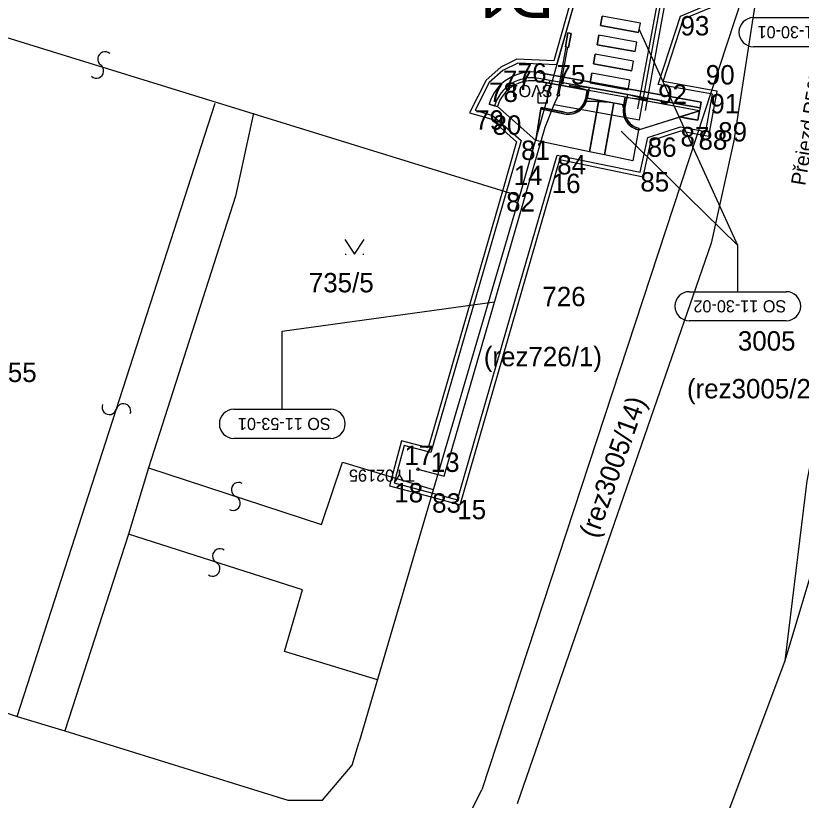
# Model space of a CAD drawing. Extents: x -728800 to -728100, y -1073200 to -1072700.
# Drawn here: x -728549.49 to -728508.97, y -1073097.26 to -1073056.8 of the extents above; entities that cross this region are included whole.
import ezdxf

# ---------------------------------------------------------------- set-up
doc = ezdxf.new("R2010")
doc.units = 0
for name, color, linetype in [('_NOR-návrh tenká obec', 7, 'Continuous'), ('_NOR-VDZ', 7, 'Continuous'), ('_NOR-šraf_+-0', 7, 'Continuous'), ('_NOR-šraf_+12', 7, 'Continuous'), ('_NOR-šraf_+6', 7, 'Continuous'), ('_NOR-šraf_bezbariéra', 7, 'Continuous'), ('_NOR-šraf_chodník', 7, 'Continuous'), ('_NOR-šraf_signální pás', 7, 'Continuous'), ('_NOR-šraf_varovný pás', 7, 'Continuous'), ('_NOR-šraf_vozovka', 7, 'Continuous'), ('_NOR-šraf_zeleň', 7, 'Continuous'), ('A2_OBVOD STAVBY', 7, 'Continuous'), ('B1_body_poloha', 7, 'Continuous'), ('B2_body_číslo', 7, 'Continuous'), ('B6_JŽM', 7, 'Continuous'), ('Default', 7, 'Continuous'), ('K_01_Hranice parcel', 7, 'Continuous'), ('K_02_Parcelní čísla', 7, 'Continuous'), ('K_03_Značky druhu pozemku', 7, 'Continuous'), ('KOS_kabelová trasa VO', 7, 'Continuous'), ('KOS_nové prvky VO', 7, 'Continuous'), ('KTA_členění PS a SO', 7, 'Continuous'), ('ZA_02_Dočasný_do_1_roku', 7, 'Continuous')]:
    doc.layers.add(name, color=color, linetype=linetype)

msp = doc.modelspace()

# ---------------------------------------------------------------- linework, layer by layer
at = {"layer": '_NOR-návrh tenká obec'}
for p, q in [((-728519.325, -1073057.313), (-728519.235, -1073056.821)), ((-728517.267, -1073057.179), (-728519.235, -1073056.821)), ((-728517.357, -1073057.671), (-728519.325, -1073057.313)), ((-728517.357, -1073057.671), (-728517.267, -1073057.179)), ((-728519.504, -1073058.296), (-728519.414, -1073057.805)), ((-728517.447, -1073058.163), (-728519.414, -1073057.805)), ((-728517.536, -1073058.655), (-728519.504, -1073058.296)), ((-728517.536, -1073058.655), (-728517.447, -1073058.163)), ((-728519.683, -1073059.28), (-728519.593, -1073058.788)), ((-728517.626, -1073059.147), (-728519.593, -1073058.788)), ((-728517.716, -1073059.639), (-728519.683, -1073059.28)), ((-728517.716, -1073059.639), (-728517.626, -1073059.147)), ((-728519.862, -1073060.264), (-728519.773, -1073059.772)), ((-728517.805, -1073060.131), (-728519.773, -1073059.772)), ((-728517.895, -1073060.623), (-728519.862, -1073060.264)), ((-728517.895, -1073060.623), (-728517.805, -1073060.131)), ((-728520.013, -1073060.643), (-728520.904, -1073060.404)), ((-728520.904, -1073060.404), (-728519.907, -1073060.51)), ((-728518.045, -1073061.002), (-728518.124, -1073061.524)), ((-728517.967, -1073061.016), (-728518.077, -1073061.532)), ((-728517.967, -1073061.016), (-728516.969, -1073061.122)), ((-728516.969, -1073061.122), (-728517.94, -1073060.869)), ((-728522.668, -1073063.246), (-728524.642, -1073061.491)), ((-728520.176, -1073061.464), (-728520.242, -1073061.417)), ((-728519.416, -1073061.159), (-728519.9, -1073063.819)), ((-728518.629, -1073061.302), (-728519.117, -1073063.982)), ((-728514.211, -1073061.701), (-728514.301, -1073062.192)), ((-728518.116, -1073061.988), (-728518.039, -1073061.965)), ((-728517.366, -1073062.682), (-728515.241, -1073062.021)), ((-728517.366, -1073062.682), (-728517.657, -1073064.284)), ((-728517.29, -1073062.698), (-728517.29, -1073062.698))]:
    msp.add_line(p, q, dxfattribs=at)
for points in [[(-728514.184, -1073061.553), (-728514.13, -1073061.258), (-728522.452, -1073059.741)], [(-728514.184, -1073061.553), (-728514.211, -1073061.701), (-728522.533, -1073060.184)], [(-728514.184, -1073061.553), (-728522.506, -1073060.036)], [(-728520.918, -1073060.478), (-728520.891, -1073060.331)], [(-728520.087, -1073061.05), (-728520.013, -1073060.643)], [(-728519.907, -1073060.51), (-728520.008, -1073061.064)], [(-728518.117, -1073061.395), (-728520.006, -1073061.051)], [(-728518.045, -1073061.002), (-728518.141, -1073061.525)], [(-728517.94, -1073060.869), (-728518.062, -1073061.539)], [(-728516.956, -1073061.048), (-728516.983, -1073061.195)], [(-728525.075, -1073061.366), (-728524.786, -1073061.45)], [(-728524.642, -1073061.491), (-728524.786, -1073061.45)], [(-728521.201, -1073061.863), (-728522.401, -1073061.607), (-728522.388, -1073061.528), (-728521.184, -1073061.785)], [(-728514.301, -1073062.192), (-728515.241, -1073062.021)], [(-728517.349, -1073062.604), (-728517.366, -1073062.682)]]:
    msp.add_lwpolyline(points, dxfattribs=at)
for centre, radius, start, end in [((-728522.865, -1073062.004), 2.3, 79.6716, 163.9062), ((-728522.865, -1073062.004), 2, 79.6716, 163.9062), ((-728522.865, -1073062.004), 1.85, 79.6716, 163.9062), ((-728521.651, -1073060.659), 1.639, 331.5487, 0.5464), ((-728522.656, -1073060.141), 2.771, 332.0344, 349.2616), ((-728520.992, -1073060.885), 1, 257.9461, 349.6716), ((-728520.992, -1073060.885), 0.92, 257.9461, 349.6716), ((-728517.157, -1073061.704), 1, 169.6716, 257.9461), ((-728517.115, -1073061.648), 1.016, 172.9753, 198.8554), ((-728517.182, -1073061.755), 0.922, 166.0226, 193.9069), ((-728517.157, -1073061.704), 0.92, 169.6716, 257.9461)]:
    msp.add_arc(centre, radius, start, end, dxfattribs=at)
at = {"layer": '_NOR-VDZ'}
for p, q in [((-728519.325, -1073057.313), (-728519.235, -1073056.821)), ((-728517.267, -1073057.179), (-728519.235, -1073056.821)), ((-728517.357, -1073057.671), (-728519.325, -1073057.313)), ((-728517.357, -1073057.671), (-728517.267, -1073057.179)), ((-728519.504, -1073058.296), (-728519.414, -1073057.805)), ((-728517.447, -1073058.163), (-728519.414, -1073057.805)), ((-728517.536, -1073058.655), (-728519.504, -1073058.296)), ((-728517.536, -1073058.655), (-728517.447, -1073058.163)), ((-728519.683, -1073059.28), (-728519.593, -1073058.788)), ((-728517.626, -1073059.147), (-728519.593, -1073058.788)), ((-728517.716, -1073059.639), (-728519.683, -1073059.28)), ((-728517.716, -1073059.639), (-728517.626, -1073059.147)), ((-728519.862, -1073060.264), (-728519.773, -1073059.772)), ((-728517.805, -1073060.131), (-728519.773, -1073059.772)), ((-728517.895, -1073060.623), (-728519.862, -1073060.264)), ((-728517.895, -1073060.623), (-728517.805, -1073060.131))]:
    msp.add_line(p, q, dxfattribs=at)
for points in [[(-728517.357, -1073057.671), (-728517.267, -1073057.179), (-728519.235, -1073056.821), (-728519.325, -1073057.313), (-728517.357, -1073057.671)], [(-728517.536, -1073058.655), (-728517.447, -1073058.163), (-728519.414, -1073057.805), (-728519.504, -1073058.296), (-728517.536, -1073058.655)], [(-728517.716, -1073059.639), (-728517.626, -1073059.147), (-728519.593, -1073058.788), (-728519.683, -1073059.28), (-728517.716, -1073059.639)], [(-728517.895, -1073060.623), (-728517.805, -1073060.131), (-728519.773, -1073059.772), (-728519.862, -1073060.264), (-728517.895, -1073060.623)]]:
    msp.add_lwpolyline(points, dxfattribs=at)
at = {"layer": '_NOR-šraf_+-0'}
for points in [[(-728518.039, -1073061.965), (-728518.077, -1073061.977), (-728518.116, -1073061.988)], [(-728517.366, -1073062.682), (-728517.349, -1073062.604)]]:
    msp.add_lwpolyline(points, dxfattribs=at)
for radius in [1, 0.92]:
    msp.add_arc((-728517.157, -1073061.704), radius, 196.5034, 257.9461, dxfattribs=at)
at = {"layer": '_NOR-šraf_+12'}
msp.add_line((-728524.786, -1073061.45), (-728524.642, -1073061.491), dxfattribs=at)
for points in [[(-728522.533, -1073060.184), (-728521.989, -1073060.283), (-728521.929, -1073060.141), (-728522.506, -1073060.036)], [(-728520.918, -1073060.478), (-728520.904, -1073060.404), (-728520.891, -1073060.331), (-728521.929, -1073060.141), (-728521.989, -1073060.283), (-728520.918, -1073060.478)], [(-728516.983, -1073061.195), (-728516.969, -1073061.122), (-728516.956, -1073061.048), (-728514.184, -1073061.553), (-728514.211, -1073061.701), (-728516.983, -1073061.195)]]:
    msp.add_lwpolyline(points, dxfattribs=at)
for radius in [2, 1.85]:
    msp.add_arc((-728522.865, -1073062.004), radius, 79.6716, 163.9062, dxfattribs=at)
at = {"layer": '_NOR-šraf_+6'}
for points in [[(-728521.184, -1073061.785), (-728522.388, -1073061.528), (-728522.401, -1073061.607)], [(-728520.176, -1073061.464), (-728520.209, -1073061.441), (-728520.211, -1073061.439), (-728520.242, -1073061.417)], [(-728522.401, -1073061.607), (-728521.201, -1073061.863)]]:
    msp.add_lwpolyline(points, dxfattribs=at)
for radius in [1, 0.92]:
    msp.add_arc((-728520.992, -1073060.885), radius, 257.9461, 324.641, dxfattribs=at)
at = {"layer": '_NOR-šraf_bezbariéra'}
msp.add_lwpolyline([(-728519.934, -1073060.658), (-728519.907, -1073060.51), (-728517.94, -1073060.869), (-728517.967, -1073061.016), (-728519.934, -1073060.658)], dxfattribs=at)
at = {"layer": '_NOR-šraf_chodník'}
for p, q in [((-728518.145, -1073061.548), (-728518.197, -1073061.381)), ((-728518.197, -1073061.381), (-728518.145, -1073061.548))]:
    msp.add_line(p, q, dxfattribs=at)
for points in [[(-728520.008, -1073061.064), (-728520.006, -1073061.051), (-728519.416, -1073061.159), (-728519.429, -1073061.233), (-728520.045, -1073061.206)], [(-728520.045, -1073061.206), (-728519.429, -1073061.233), (-728519.9, -1073063.819), (-728522.668, -1073063.246)], [(-728519.117, -1073063.982), (-728518.629, -1073061.302), (-728518.197, -1073061.381)], [(-728518.197, -1073061.381), (-728518.117, -1073061.395), (-728518.141, -1073061.525)], [(-728522.668, -1073063.246), (-728522.401, -1073061.607), (-728521.201, -1073061.863)], [(-728517.37, -1073062.681), (-728517.366, -1073062.682), (-728517.657, -1073064.284), (-728519.117, -1073063.982)]]:
    msp.add_lwpolyline(points, dxfattribs=at)
for centre, start, end in [((-728520.992, -1073060.885), 341.2678, 349.6716), ((-728520.992, -1073060.885), 257.9461, 324.641), ((-728520.992, -1073060.885), 324.641, 341.2678), ((-728517.157, -1073061.704), 169.6716, 171.0403), ((-728517.157, -1073061.704), 171.0403, 196.5034), ((-728517.157, -1073061.704), 196.5034, 257.6848)]:
    msp.add_arc(centre, 1, start, end, dxfattribs=at)
at = {"layer": '_NOR-šraf_signální pás'}
for points in [[(-728519.429, -1073061.233), (-728518.877, -1073061.257), (-728518.629, -1073061.302), (-728519.117, -1073063.982), (-728519.9, -1073063.819), (-728519.429, -1073061.233)], [(-728519.416, -1073061.159), (-728518.877, -1073061.257), (-728519.429, -1073061.233), (-728519.416, -1073061.159)]]:
    msp.add_lwpolyline(points, dxfattribs=at)
at = {"layer": '_NOR-šraf_varovný pás'}
msp.add_lwpolyline([(-728520.006, -1073061.051), (-728519.416, -1073061.159), (-728518.629, -1073061.302), (-728518.117, -1073061.395), (-728518.045, -1073061.002), (-728519.934, -1073060.658), (-728520.006, -1073061.051), (-728520.006, -1073061.051)], dxfattribs=at)
at = {"layer": '_NOR-šraf_vozovka'}
for points in [[(-728522.452, -1073059.741), (-728514.13, -1073061.258), (-728514.184, -1073061.553), (-728516.956, -1073061.048), (-728517.94, -1073060.869), (-728519.907, -1073060.51), (-728522.506, -1073060.036)], [(-728524.786, -1073061.45), (-728525.075, -1073061.366), (-728525.075, -1073061.366)]]:
    msp.add_lwpolyline(points, dxfattribs=at)
for radius in [2.3, 2]:
    msp.add_arc((-728522.865, -1073062.004), radius, 79.6716, 163.9062, dxfattribs=at)
at = {"layer": '_NOR-šraf_zeleň'}
for points in [[(-728522.533, -1073060.184), (-728522.115, -1073060.26), (-728522.341, -1073060.799), (-728522.56, -1073060.799), (-728522.56, -1073061.299), (-728522.31, -1073061.299), (-728522.06, -1073061.299), (-728522.06, -1073060.799), (-728522.07, -1073060.799), (-728521.863, -1073060.306), (-728520.013, -1073060.643), (-728520.087, -1073061.05)], [(-728517.349, -1073062.604), (-728517.366, -1073062.682), (-728514.211, -1073061.701), (-728517.967, -1073061.016), (-728518.062, -1073061.539)], [(-728521.184, -1073061.785), (-728522.388, -1073061.528), (-728522.401, -1073061.607), (-728522.668, -1073063.246), (-728524.642, -1073061.491)], [(-728514.832, -1073062.096), (-728514.301, -1073062.192), (-728514.211, -1073061.701), (-728515.241, -1073062.021), (-728514.832, -1073062.096), (-728514.832, -1073062.096)]]:
    msp.add_lwpolyline(points, dxfattribs=at)
for centre, radius, start, end in [((-728522.865, -1073062.004), 1.85, 79.6716, 163.9062), ((-728520.992, -1073060.885), 0.92, 324.641, 349.6716), ((-728520.992, -1073060.885), 0.92, 257.9461, 324.641), ((-728517.157, -1073061.704), 0.92, 169.6716, 196.5034), ((-728517.157, -1073061.704), 0.92, 196.5034, 257.9461)]:
    msp.add_arc(centre, radius, start, end, dxfattribs=at)
at = {"layer": 'A2_OBVOD STAVBY'}
msp.add_lwpolyline([(-728520.331, -1073054.186), (-728521.735, -1073059.131), (-728523.635, -1073059.049), (-728524.468, -1073059.462), (-728525.229, -1073060.125), (-728526.082, -1073061.804), (-728524.989, -1073062.12), (-728523.652, -1073063.308), (-728524.386, -1073065.843), (-728528.221, -1073079.089), (-728529.585, -1073078.721), (-728530.21, -1073081.039), (-728528.058, -1073081.619), (-728526.571, -1073082.019), (-728521.417, -1073064.22), (-728517.12, -1073065.11), (-728516.715, -1073063.238), (-728515.187, -1073062.742), (-728514.306, -1073062.903), (-728513.737, -1073063.007), (-728513.316, -1073060.695), (-728513.62, -1073060.639), (-728516.085, -1073060.19), (-728515.041, -1073056.967), (-728511.798, -1073055.597)], dxfattribs=at)
at = {"layer": 'B1_body_poloha'}
for p, q in [((-728515.2, -1073056.82), (-728515.2, -1073056.82)), ((-728523.59, -1073059.25), (-728523.59, -1073059.25)), ((-728521.59, -1073059.34), (-728521.59, -1073059.34)), ((-728524.36, -1073059.63), (-728524.36, -1073059.63)), ((-728525.07, -1073060.25), (-728525.07, -1073060.25)), ((-728516.35, -1073060.35), (-728516.35, -1073060.35)), ((-728513.66, -1073060.84), (-728513.66, -1073060.84)), ((-728513.55, -1073060.86), (-728513.55, -1073060.86)), ((-728525.79, -1073061.68), (-728525.79, -1073061.68)), ((-728524.89, -1073061.94), (-728524.89, -1073061.94)), ((-728515.2, -1073062.54), (-728515.2, -1073062.54)), ((-728514.27, -1073062.71), (-728514.27, -1073062.71)), ((-728516.89, -1073063.08), (-728516.89, -1073063.08)), ((-728513.9, -1073062.77), (-728513.9, -1073062.77)), ((-728523.42, -1073063.24), (-728523.42, -1073063.24)), ((-728521.56, -1073063.99), (-728521.56, -1073063.99)), ((-728523.8, -1073064.54), (-728523.8, -1073064.54)), ((-728521.84, -1073064.95), (-728521.84, -1073064.95)), ((-728517.27, -1073064.87), (-728517.27, -1073064.87)), ((-728524.19, -1073065.9), (-728524.19, -1073065.9)), ((-728529.44, -1073078.97), (-728529.44, -1073078.97)), ((-728528.08, -1073079.33), (-728528.08, -1073079.33)), ((-728529.96, -1073080.9), (-728529.96, -1073080.9)), ((-728528.01, -1073081.43), (-728528.01, -1073081.43)), ((-728526.71, -1073081.77), (-728526.71, -1073081.77))]:
    msp.add_line(p, q, dxfattribs=at)
at = {"layer": 'K_01_Hranice parcel'}
for p, q in [((-728510.66, -1073051.71), (-728525.44, -1073096.73)), ((-728519.8, -1073053.05), (-728523.51, -1073066.11)), ((-728523.51, -1073066.11), (-728551.004, -1073057.612)), ((-728549.411, -1073092.938), (-728539.196, -1073061.32)), ((-728523.51, -1073066.11), (-728531.77, -1073094.25)), ((-728513.61, -1073068.54), (-728523.622, -1073097.442))]:
    msp.add_line(p, q, dxfattribs=at)
for points in [[(-728510.66, -1073051.71), (-728512.45, -1073063.25), (-728513.61, -1073068.54)], [(-728503.24, -1073052.34), (-728506.32, -1073069.08), (-728508.676, -1073080.788), (-728509.816, -1073090.065)], [(-728537.214, -1073061.821), (-728538.146, -1073066.111), (-728542.63, -1073080.116), (-728543.663, -1073083.544), (-728546.946, -1073093.688)], [(-728504.87, -1073073.55), (-728509.816, -1073090.065), (-728516.822, -1073108.739), (-728518.032, -1073119.517), (-728508.074, -1073118.154), (-728495.997, -1073074.887)], [(-728579.353, -1073076.384), (-728583.789, -1073102.649), (-728543.041, -1073118.426), (-728537.574, -1073120.982), (-728525.44, -1073096.73)], [(-728542.63, -1073080.116), (-728533.711, -1073083.038), (-728532.624, -1073079.827), (-728527.948, -1073081.228)], [(-728569.191, -1073080.263), (-728570.895, -1073085.354), (-728570.206, -1073086.158), (-728561.23, -1073088.922), (-728549.411, -1073092.938), (-728546.946, -1073093.688), (-728535.442, -1073097.263), (-728533.661, -1073097.263), (-728532.131, -1073095.453), (-728531.77, -1073094.25)], [(-728530.83, -1073091.046), (-728535.614, -1073089.594), (-728534.69, -1073086.411), (-728543.663, -1073083.544)]]:
    msp.add_lwpolyline(points, dxfattribs=at)
at = {"layer": 'K_03_Značky druhu pozemku'}
for p, q in [((-728532.489, -1073069.096), (-728532.439, -1073069.096)), ((-728531.589, -1073069.096), (-728531.539, -1073069.096))]:
    msp.add_line(p, q, dxfattribs=at)
msp.add_lwpolyline([(-728532.514, -1073068.346), (-728532.014, -1073069.096), (-728531.514, -1073068.346)], dxfattribs=at)
for centre, start, end in [((-728544.88, -1073059.037), 47.7437, 234.0408), ((-728545.322, -1073059.646), 227.7437, 54.0408), ((-728544.654, -1073076.994), 158.8659, 345.163), ((-728543.927, -1073077.187), 338.8659, 165.163), ((-728537.988, -1073081.248), 60.9548, 247.2518), ((-728538.279, -1073081.942), 240.9548, 67.2518), ((-728538.956, -1073084.672), 54.1364, 240.4334), ((-728539.328, -1073085.327), 234.1364, 60.4334)]:
    msp.add_arc(centre, 0.376, start, end, dxfattribs=at)
at = {"layer": 'KOS_kabelová trasa VO'}
for p, q in [((-728515.932, -1073053.526), (-728517.409, -1073061.613)), ((-728515.538, -1073053.598), (-728517.015, -1073061.684))]:
    msp.add_line(p, q, dxfattribs=at)
for points in [[(-728528.739, -1073080.192), (-728527.396, -1073080.554), (-728522.184, -1073062.556), (-728521.71, -1073061.375), (-728517.306, -1073062.171), (-728515.639, -1073053.015), (-728515.016, -1073053.113), (-728515.09, -1073053.601)], [(-728521.71, -1073061.375), (-728521.499, -1073060.881)]]:
    msp.add_lwpolyline(points, dxfattribs=at)
at = {"layer": 'KOS_nové prvky VO'}
for p, q in [((-728521.527, -1073060.82), (-728521.089, -1073058.414)), ((-728521.452, -1073060.834), (-728521.014, -1073058.428))]:
    msp.add_line(p, q, dxfattribs=at)
msp.add_lwpolyline([(-728521.135, -1073058.406), (-728521.003, -1073057.682), (-728520.836, -1073057.712), (-728520.968, -1073058.436)], close=True, dxfattribs=at)
msp.add_lwpolyline([(-728520.968, -1073058.436), (-728520.836, -1073057.712), (-728521.003, -1073057.682), (-728521.135, -1073058.406), (-728520.968, -1073058.436)], dxfattribs=at)
for centre in [(-728521.499, -1073060.881), (-728528.739, -1073080.192)]:
    msp.add_circle(centre, 0.0665, dxfattribs=at)
at = {"layer": 'KTA_členění PS a SO'}
for p, q in [((-728512.245, -1073068.65), (-728517.324, -1073057.492)), ((-728512.245, -1073068.65), (-728518.265, -1073062.753)), ((-728512.245, -1073071.034), (-728512.245, -1073068.65)), ((-728535.738, -1073073.063), (-728524.792, -1073071.553)), ((-728535.738, -1073077.101), (-728535.738, -1073073.063))]:
    msp.add_line(p, q, dxfattribs=at)
for points in [[(-728511.438, -1073056.9), (-728506.438, -1073056.9)], [(-728506.438, -1073058.4), (-728511.438, -1073058.4)], [(-728514.745, -1073071.034), (-728509.745, -1073071.034)], [(-728509.745, -1073072.534), (-728514.745, -1073072.534)], [(-728538.238, -1073077.101), (-728533.238, -1073077.101)], [(-728533.238, -1073078.601), (-728538.238, -1073078.601)]]:
    msp.add_lwpolyline(points, dxfattribs=at)
for centre, start, end in [((-728511.432, -1073057.65), 90.4529, 269.5471), ((-728514.739, -1073071.784), 90.4529, 269.5471), ((-728509.751, -1073071.784), 270.4529, 89.5471), ((-728538.232, -1073077.851), 90.4529, 269.5471), ((-728533.244, -1073077.851), 270.4529, 89.5471)]:
    msp.add_arc(centre, 0.75, start, end, dxfattribs=at)
at = {"layer": 'ZA_02_Dočasný_do_1_roku'}
msp.add_lwpolyline([(-728520.113, -1073054.153), (-728521.586, -1073059.338), (-728523.592, -1073059.251), (-728524.356, -1073059.629), (-728525.069, -1073060.25), (-728525.794, -1073061.679), (-728524.89, -1073061.94), (-728523.424, -1073063.243), (-728526.138, -1073072.616), (-728528.083, -1073079.333), (-728529.444, -1073078.966), (-728529.965, -1073080.897), (-728526.708, -1073081.775), (-728524.133, -1073072.881), (-728521.558, -1073063.987), (-728517.274, -1073064.874), (-728516.886, -1073063.083), (-728515.201, -1073062.537), (-728513.898, -1073062.774), (-728513.549, -1073060.856), (-728516.346, -1073060.346), (-728515.203, -1073056.818), (-728511.189, -1073055.123)], dxfattribs=at)

# ---------------------------------------------------------------- texts
at = {"layer": 'B2_body_číslo'}
for s, p in [('93', (-728515.2, -1073057.82)), ('76', (-728523.59, -1073060.25)), ('75', (-728521.59, -1073060.34)), ('90', (-728513.892, -1073060.347)), ('77', (-728524.36, -1073060.63)), ('78', (-728525.07, -1073061.25)), ('92', (-728516.35, -1073061.35)), ('91', (-728513.66, -1073061.84)), ('79', (-728525.79, -1073062.68)), ('80', (-728524.89, -1073062.94)), ('89', (-728513.254, -1073063.292)), ('87', (-728515.2, -1073063.54)), ('88', (-728514.27, -1073063.71)), ('86', (-728516.89, -1073064.08)), ('81', (-728523.42, -1073064.24)), ('84', (-728521.56, -1073064.99)), ('14', (-728523.8, -1073065.54)), ('16', (-728521.84, -1073065.95)), ('85', (-728517.27, -1073065.87)), ('82', (-728524.19, -1073066.9)), ('17', (-728529.44, -1073079.97)), ('13', (-728528.08, -1073080.33)), ('18', (-728529.96, -1073081.9)), ('83', (-728528.01, -1073082.43)), ('15', (-728526.71, -1073082.77))]:
    msp.add_text(s, height=1, dxfattribs=at).set_placement(p)
at = {"layer": 'B6_JŽM'}
msp.add_text('Přejezd P5678', height=0.75, rotation=80.4567, dxfattribs=at).set_placement((-728508.77, -1073065.594))
at = {"layer": 'Default'}
msp.add_text('TY02195', height=0.625, rotation=180, dxfattribs=at).set_placement((-728528.905, -1073080.207))
at = {"layer": 'K_02_Parcelní čísla'}
for s, p in [('735/5', (-728534.368, -1073071.069)), ('726', (-728522.324, -1073071.783)), ('3005', (-728512.241, -1073074.073)), ('(rez726/1)', (-728525.345, -1073074.879)), ('855', (-728550.635, -1073075.695)), ('(rez3005/21)', (-728514.867, -1073076.536))]:
    msp.add_text(s, height=1, dxfattribs=at).set_placement(p)
msp.add_text('(rez3005/14)', height=1, rotation=70.428, dxfattribs=at).set_placement((-728519.504, -1073083.803))
at = {"layer": 'KOS_nové prvky VO'}
msp.add_text('SVO1', height=0.625, rotation=180, dxfattribs=at).set_placement((-728521.785, -1073060.374))
at = {"layer": 'KTA_členění PS a SO'}
for s, p in [('SO 11-30-01', (-728506.439, -1073057.341)), ('SO 11-30-02', (-728509.746, -1073071.476)), ('SO 11-53-01', (-728533.239, -1073077.543))]:
    msp.add_text(s, height=0.625, rotation=180, dxfattribs=at).set_placement(p)
at = {"layer": 'ZA_02_Dočasný_do_1_roku'}
msp.add_text('D1', height=2.5, rotation=180, dxfattribs=at).set_placement((-728521.71, -1073054.418))

doc.saveas('drawing.dxf')
